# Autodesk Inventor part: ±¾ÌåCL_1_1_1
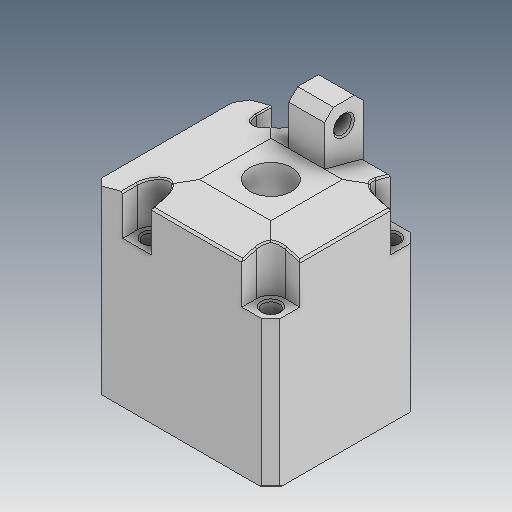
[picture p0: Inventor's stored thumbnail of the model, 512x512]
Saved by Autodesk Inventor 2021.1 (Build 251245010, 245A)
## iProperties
Created: 2019-04
Part Number: ±¾ÌåCL_1_1_1
Material: Ogólny
Document SubType Name: Modeling
Designer: user
Density: 1 g/cm^3
Appearance: Domyślna
Author: user
Revision Number: ÈÎºÎ
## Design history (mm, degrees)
feature "ÊäÈë1"
feature "ÊäÈë2"
node "Bryła1"
node "Bryła2"
